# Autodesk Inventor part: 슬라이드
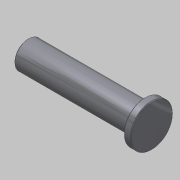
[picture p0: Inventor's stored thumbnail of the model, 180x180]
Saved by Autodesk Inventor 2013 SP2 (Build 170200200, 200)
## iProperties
Created: 2013-06
Part Number: 슬라이드
Document SubType Name: Modeling
Designer: SeoGD™[esajin.kr]
Density: 1 g/cm^3
Material: 일반
Mass: 203.978 g
Surface Area: 269.019 cm^2
Volume: 203.978 cm^3
Author: SeoGD™[esajin.kr]
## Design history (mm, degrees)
sketch "스케치1"
  geometry: L1 (-75, 162)-(-75, 58) reference; L2 (-148, 110)-(22, 110); L3 (-148, 110)-(-148, 129); L4 (-148, 129)-(12, 129); L5 (12, 129)-(12, 139); L6 (12, 139)-(22, 139); L7 (22, 139)-(22, 110); 2 further points
  constraints: 12 end point, 3 parallel, 3 perpendicular, 1 midpoint, 1 point on line
  dimensions: "d0" = 58 diameter of L6 L2; "d1" = 38 diameter of L4 L2; "d2" = 10 distance of L5.end L6.end; "d3" = 170 distance of L2.start L2.end; "d4" = 73 distance between parallel lines of L3 L1
revolve "회전1" sketch "스케치1" stored, may be unused: angle "d5" = 90 deg
hole "구멍1" diameter "d11" = 13.376; stored, may be unused: countersink angle "d15" = 90 deg, drill point angle "d17" = 118 deg; dims "d9" = 10, "d10" = 10, "d12" = 22, "d13" = 4, "d14" = 2, "d16" = 25
chamfer "모따기1" distance "d6" = 1; stored, may be unused: second distance "d7" = 2, angle "d8" = 45 deg
node "솔리드1"
node "참조1"
